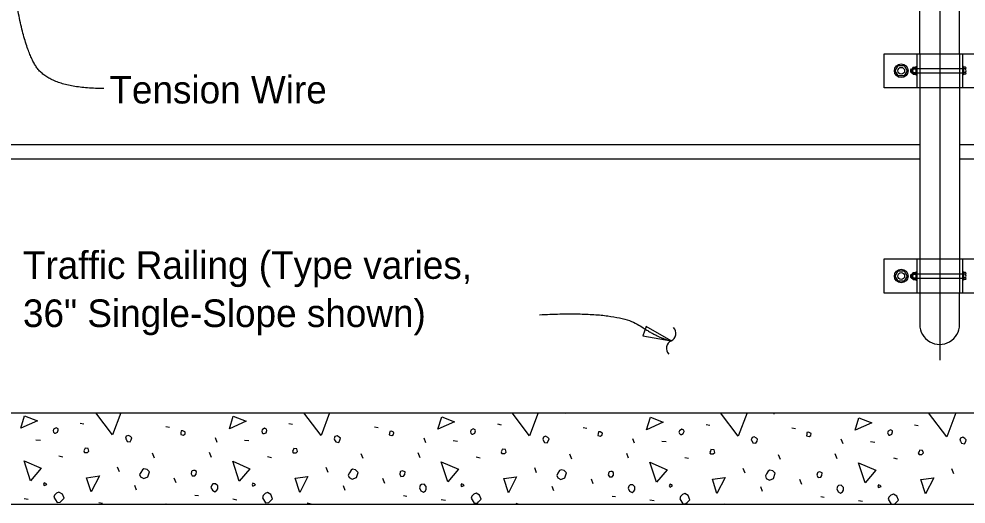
# Model space of a CAD drawing. Extents: x 0 to 41.1, y 0 to 26.4.
# Drawn here: x 5.48 to 12.4, y 13.8 to 17.35 of the extents above; entities that cross this region are included whole.
import ezdxf

# ---------------------------------------------------------------- set-up
doc = ezdxf.new("R2010")
doc.units = 0
for name, color, linetype in [('CL_Major', 7, 'Continuous'), ('Dimension', 7, 'Continuous'), ('Miscellaneous', 7, 'Continuous'), ('SteelMisc', 7, 'Continuous'), ('SteelMisc_h', 7, 'Continuous'), ('SupstrConc', 7, 'Continuous'), ('TextStructures', 7, 'Continuous')]:
    doc.layers.add(name, color=color, linetype=linetype)

msp = doc.modelspace()

# ---------------------------------------------------------------- linework, layer by layer
at = {"layer": 'CL_Major'}
msp.add_line((12.2062, 25.2199), (12.2062, 14.8548), dxfattribs=at)
at = {"layer": 'Dimension'}
msp.add_lwpolyline([(10.2447, 14.9952), (10.0611, 15.0997), (10.0369, 15.0334)], close=True, dxfattribs=at)
for centre, start, end in [((10.2205, 15.0503), 294.14658, 45.87379), ((10.2692, 14.9415), 114.14657, 225.87379)]:
    msp.add_arc(centre, 0.0596, start, end, dxfattribs=at)
for points in [[(6.1, 16.8398), (5.7021, 16.8398), (5.4981, 17.1768), (5.4369, 17.6337)], [(9.284, 15.1869), (9.8469, 15.2152), (10.1683, 15.0071), (10.2449, 14.9959)]]:
    msp.add_open_spline(points, degree=2, dxfattribs=at)
at = {"layer": 'Miscellaneous'}
for p, q in [((11.9986, 16.9625), (11.9986, 16.9746)), ((12.0044, 16.9625), (12.0044, 16.9746)), ((11.9986, 15.4625), (11.9986, 15.4746)), ((12.0044, 15.4625), (12.0044, 15.4746)), ((7.9504, 14.4659), (7.9491, 14.4695)), ((9.4742, 14.4624), (9.4716, 14.4695)), ((10.9981, 14.4588), (10.9942, 14.4695)), ((5.9281, 14.3952), (5.9546, 14.3899)), ((7.4519, 14.3917), (7.4784, 14.3864)), ((6.5539, 14.3705), (6.5804, 14.3652)), ((8.0777, 14.3669), (8.1042, 14.3616)), ((8.9757, 14.3881), (9.0023, 14.3828)), ((9.6015, 14.3634), (9.628, 14.3581)), ((10.4996, 14.3846), (10.5261, 14.3793)), ((11.1253, 14.3599), (11.1519, 14.3545)), ((12.0234, 14.3811), (12.0499, 14.3758)), ((5.6046, 14.2732), (5.6364, 14.2697)), ((6.9287, 14.2538), (6.9163, 14.2874)), ((7.1284, 14.2697), (7.1602, 14.2662)), ((8.4525, 14.2502), (8.4401, 14.2838)), ((8.6522, 14.2662), (8.6841, 14.2626)), ((9.9763, 14.2467), (9.9639, 14.2803)), ((10.1761, 14.2626), (10.2079, 14.2591)), ((11.5001, 14.2432), (11.4877, 14.2768)), ((11.6999, 14.2591), (11.7317, 14.2556)), ((5.7725, 14.1548), (5.8008, 14.1477)), ((6.4708, 14.1389), (6.4567, 14.1742)), ((6.8862, 14.1442), (6.8721, 14.1795)), ((7.2964, 14.1513), (7.3246, 14.1442)), ((7.9946, 14.1353), (7.9805, 14.1707)), ((8.4101, 14.1406), (8.3959, 14.176)), ((8.8202, 14.1477), (8.8485, 14.1406)), ((9.5184, 14.1318), (9.5043, 14.1672)), ((9.9339, 14.1371), (9.9197, 14.1725)), ((10.344, 14.1442), (10.3723, 14.1371)), ((11.0423, 14.1283), (11.0281, 14.1636)), ((11.4577, 14.1336), (11.4435, 14.1689)), ((11.8678, 14.1406), (11.8961, 14.1336)), ((6.2145, 14.0381), (6.2003, 14.0735)), ((7.7383, 14.0346), (7.7242, 14.0699)), ((9.2621, 14.031), (9.248, 14.0664)), ((10.7859, 14.0275), (10.7718, 14.0629)), ((12.3097, 14.024), (12.2956, 14.0593)), ((6.6281, 13.9568), (6.614, 13.9922)), ((8.152, 13.9533), (8.1378, 13.9886)), ((9.6758, 13.9497), (9.6616, 13.9851)), ((11.1996, 13.9462), (11.1854, 13.9815)), ((6.34, 13.9055), (6.3276, 13.9391)), ((7.8638, 13.902), (7.8514, 13.9356)), ((9.3876, 13.8985), (9.3753, 13.9321)), ((10.9114, 13.8949), (10.8991, 13.9285)), ((5.518, 13.8437), (5.548, 13.8384)), ((6.766, 13.8684), (6.7908, 13.8649)), ((7.0418, 13.8401), (7.0719, 13.8348)), ((8.2898, 13.8649), (8.3146, 13.8613)), ((9.8137, 13.8613), (9.8384, 13.8578)), ((11.3375, 13.8578), (11.3622, 13.8543)), ((6.0625, 13.8154), (6.0907, 13.8083)), ((7.5863, 13.8118), (7.6146, 13.8048)), ((8.5656, 13.8366), (8.5957, 13.8313)), ((9.1101, 13.8083), (9.1322, 13.8028)), ((10.0894, 13.8331), (10.1195, 13.8278)), ((10.6339, 13.8048), (10.6418, 13.8028)), ((11.6132, 13.8295), (11.6433, 13.8242))]:
    msp.add_line(p, q, dxfattribs=at)
for points in [[(6.1632, 14.3086), (6.041, 14.4695)], [(6.2233, 14.4695), (6.1632, 14.3086)], [(7.687, 14.305), (7.5621, 14.4695)], [(7.7485, 14.4695), (7.687, 14.305)], [(9.2109, 14.3015), (9.0832, 14.4695)], [(9.2736, 14.4695), (9.2109, 14.3015)], [(10.7347, 14.298), (10.6043, 14.4695)], [(10.7988, 14.4695), (10.7347, 14.298)], [(12.2585, 14.2944), (12.1255, 14.4695)], [(12.3239, 14.4695), (12.2585, 14.2944)], [(5.4932, 14.3563), (5.5215, 14.4482), (5.6152, 14.4111), (5.4932, 14.3563)], [(7.0171, 14.3528), (7.0453, 14.4447), (7.139, 14.4076), (7.0171, 14.3528)], [(8.5409, 14.3492), (8.5692, 14.4412), (8.6628, 14.404), (8.5409, 14.3492)], [(10.0647, 14.3457), (10.093, 14.4376), (10.1867, 14.4005), (10.0647, 14.3457)], [(11.5885, 14.3422), (11.6168, 14.4341), (11.7105, 14.397), (11.5885, 14.3422)], [(5.7407, 14.321), (5.7478, 14.321), (5.7619, 14.328), (5.7672, 14.3439), (5.7655, 14.3528), (5.7513, 14.3599), (5.7337, 14.3492), (5.7301, 14.3386), (5.7337, 14.328), (5.7407, 14.321)], [(6.6617, 14.3121), (6.6812, 14.3068), (6.6935, 14.3157), (6.6953, 14.328), (6.6918, 14.3316), (6.6776, 14.3386), (6.6653, 14.3369), (6.6635, 14.3245), (6.6617, 14.3121)], [(7.2645, 14.3174), (7.2716, 14.3174), (7.2858, 14.3245), (7.2911, 14.3404), (7.2893, 14.3492), (7.2751, 14.3563), (7.2575, 14.3457), (7.2539, 14.3351), (7.2575, 14.3245), (7.2645, 14.3174)], [(8.1855, 14.3086), (8.205, 14.3033), (8.2174, 14.3121), (8.2191, 14.3245), (8.2156, 14.328), (8.2015, 14.3351), (8.1891, 14.3333), (8.1873, 14.321), (8.1855, 14.3086)], [(8.7884, 14.3139), (8.7954, 14.3139), (8.8096, 14.321), (8.8149, 14.3369), (8.8131, 14.3457), (8.799, 14.3528), (8.7813, 14.3422), (8.7777, 14.3316), (8.7813, 14.321), (8.7884, 14.3139)], [(9.7094, 14.305), (9.7288, 14.2997), (9.7412, 14.3086), (9.7429, 14.321), (9.7394, 14.3245), (9.7253, 14.3316), (9.7129, 14.3298), (9.7111, 14.3174), (9.7094, 14.305)], [(10.3122, 14.3104), (10.3192, 14.3104), (10.3334, 14.3174), (10.3387, 14.3333), (10.3369, 14.3422), (10.3228, 14.3492), (10.3051, 14.3386), (10.3016, 14.328), (10.3051, 14.3174), (10.3122, 14.3104)], [(11.2332, 14.3015), (11.2526, 14.2962), (11.265, 14.305), (11.2668, 14.3174), (11.2632, 14.321), (11.2491, 14.328), (11.2367, 14.3263), (11.2349, 14.3139), (11.2332, 14.3015)], [(11.836, 14.3068), (11.8431, 14.3068), (11.8572, 14.3139), (11.8625, 14.3298), (11.8607, 14.3386), (11.8466, 14.3457), (11.8289, 14.3351), (11.8254, 14.3245), (11.8289, 14.3139), (11.836, 14.3068)], [(6.2622, 14.2768), (6.2711, 14.2609), (6.2923, 14.2573), (6.3011, 14.2732), (6.3046, 14.2874), (6.2958, 14.2962), (6.2799, 14.305), (6.264, 14.2997), (6.2587, 14.2838), (6.2622, 14.2768)], [(7.786, 14.2732), (7.7949, 14.2573), (7.8161, 14.2538), (7.8249, 14.2697), (7.8285, 14.2838), (7.8196, 14.2927), (7.8037, 14.3015), (7.7878, 14.2962), (7.7825, 14.2803), (7.786, 14.2732)], [(9.3098, 14.2697), (9.3187, 14.2538), (9.3399, 14.2502), (9.3487, 14.2662), (9.3523, 14.2803), (9.3434, 14.2891), (9.3275, 14.298), (9.3116, 14.2927), (9.3063, 14.2768), (9.3098, 14.2697)], [(10.8337, 14.2662), (10.8425, 14.2502), (10.8637, 14.2467), (10.8726, 14.2626), (10.8761, 14.2768), (10.8672, 14.2856), (10.8513, 14.2944), (10.8354, 14.2891), (10.8301, 14.2732), (10.8337, 14.2662)], [(12.3575, 14.2626), (12.3663, 14.2467), (12.3875, 14.2432), (12.3964, 14.2591), (12.3999, 14.2732), (12.3911, 14.2821), (12.3752, 14.2909), (12.3592, 14.2856), (12.3539, 14.2697), (12.3575, 14.2626)], [(5.9599, 14.1795), (5.9811, 14.1795), (5.9917, 14.1901), (5.9864, 14.2096), (5.9635, 14.2114), (5.9599, 14.2008), (5.9546, 14.1919), (5.9599, 14.1795), (5.9564, 14.1831)], [(7.4837, 14.176), (7.505, 14.176), (7.5156, 14.1866), (7.5103, 14.2061), (7.4873, 14.2078), (7.4837, 14.1972), (7.4784, 14.1884), (7.4837, 14.176), (7.4802, 14.1795)], [(9.0076, 14.1725), (9.0288, 14.1725), (9.0394, 14.1831), (9.0341, 14.2025), (9.0111, 14.2043), (9.0076, 14.1937), (9.0023, 14.1848), (9.0076, 14.1725), (9.004, 14.176)], [(10.5314, 14.1689), (10.5526, 14.1689), (10.5632, 14.1795), (10.5579, 14.199), (10.5349, 14.2008), (10.5314, 14.1901), (10.5261, 14.1813), (10.5314, 14.1689), (10.5278, 14.1725)], [(12.0552, 14.1654), (12.0764, 14.1654), (12.087, 14.176), (12.0817, 14.1954), (12.0587, 14.1972), (12.0552, 14.1866), (12.0499, 14.1778), (12.0552, 14.1654), (12.0517, 14.1689)], [(5.5657, 13.9727), (5.518, 14.1194), (5.6435, 14.0646), (5.5657, 13.9727)], [(7.0895, 13.9692), (7.0418, 14.1159), (7.1673, 14.0611), (7.0895, 13.9692)], [(6.3683, 14.001), (6.3913, 13.9886), (6.4213, 14.001), (6.4337, 14.0381), (6.416, 14.0558), (6.393, 14.0611), (6.3824, 14.054), (6.37, 14.0346), (6.3612, 14.0187), (6.3683, 14.001)], [(6.7377, 14.024), (6.7466, 14.0081), (6.766, 14.0098), (6.7749, 14.0222), (6.7766, 14.0417), (6.7643, 14.047), (6.7554, 14.0487), (6.7448, 14.0452), (6.7413, 14.0417), (6.7377, 14.024)], [(7.8921, 13.9975), (7.9151, 13.9851), (7.9451, 13.9975), (7.9575, 14.0346), (7.9398, 14.0523), (7.9168, 14.0576), (7.9062, 14.0505), (7.8939, 14.031), (7.885, 14.0151), (7.8921, 13.9975)], [(8.6133, 13.9656), (8.5656, 14.1124), (8.6911, 14.0576), (8.6133, 13.9656)], [(9.4159, 13.9939), (9.4389, 13.9815), (9.4689, 13.9939), (9.4813, 14.031), (9.4636, 14.0487), (9.4407, 14.054), (9.4301, 14.047), (9.4177, 14.0275), (9.4088, 14.0116), (9.4159, 13.9939)], [(10.1372, 13.9621), (10.0894, 14.1088), (10.2149, 14.054), (10.1372, 13.9621)], [(10.9397, 13.9904), (10.9627, 13.978), (10.9928, 13.9904), (11.0051, 14.0275), (10.9875, 14.0452), (10.9645, 14.0505), (10.9539, 14.0434), (10.9415, 14.024), (10.9327, 14.0081), (10.9397, 13.9904)], [(11.661, 13.9586), (11.6132, 14.1053), (11.7388, 14.0505), (11.661, 13.9586)], [(6.0077, 13.8914), (5.9741, 13.9957), (6.0678, 14.0081), (6.0077, 13.8914)], [(7.5315, 13.8879), (7.4979, 13.9922), (7.5916, 14.0045), (7.5315, 13.8879)], [(8.2616, 14.0204), (8.2704, 14.0045), (8.2898, 14.0063), (8.2987, 14.0187), (8.3005, 14.0381), (8.2881, 14.0434), (8.2792, 14.0452), (8.2686, 14.0417), (8.2651, 14.0381), (8.2616, 14.0204)], [(9.0553, 13.8843), (9.0217, 13.9886), (9.1154, 14.001), (9.0553, 13.8843)], [(9.7854, 14.0169), (9.7942, 14.001), (9.8137, 14.0028), (9.8225, 14.0151), (9.8243, 14.0346), (9.8119, 14.0399), (9.8031, 14.0417), (9.7924, 14.0381), (9.7889, 14.0346), (9.7854, 14.0169)], [(10.5791, 13.8808), (10.5455, 13.9851), (10.6392, 13.9975), (10.5791, 13.8808)], [(11.3092, 14.0134), (11.318, 13.9975), (11.3375, 13.9992), (11.3463, 14.0116), (11.3481, 14.031), (11.3357, 14.0363), (11.3269, 14.0381), (11.3163, 14.0346), (11.3127, 14.031), (11.3092, 14.0134)], [(12.1029, 13.8772), (12.0693, 13.9815), (12.163, 13.9939), (12.1029, 13.8772)], [(5.6647, 13.9374), (5.6842, 13.9462), (5.6771, 13.9533), (5.6647, 13.9586), (5.6594, 13.9462), (5.6647, 13.9374)], [(6.8827, 13.925), (6.8933, 13.9038), (6.911, 13.8932), (6.9251, 13.9038), (6.9322, 13.9144), (6.9322, 13.9356), (6.9163, 13.9515), (6.8968, 13.9497), (6.888, 13.9409), (6.8827, 13.925)], [(7.1885, 13.9338), (7.208, 13.9427), (7.2009, 13.9497), (7.1885, 13.955), (7.1832, 13.9427), (7.1885, 13.9338)], [(8.4065, 13.9214), (8.4171, 13.9002), (8.4348, 13.8896), (8.4489, 13.9002), (8.456, 13.9108), (8.456, 13.9321), (8.4401, 13.948), (8.4207, 13.9462), (8.4118, 13.9374), (8.4065, 13.9214)], [(8.7123, 13.9303), (8.7318, 13.9391), (8.7247, 13.9462), (8.7123, 13.9515), (8.707, 13.9391), (8.7123, 13.9303)], [(9.9303, 13.9179), (9.9409, 13.8967), (9.9586, 13.8861), (9.9728, 13.8967), (9.9798, 13.9073), (9.9798, 13.9285), (9.9639, 13.9444), (9.9445, 13.9427), (9.9356, 13.9338), (9.9303, 13.9179)], [(10.2362, 13.9267), (10.2556, 13.9356), (10.2485, 13.9427), (10.2362, 13.948), (10.2309, 13.9356), (10.2362, 13.9267)], [(11.4541, 13.9144), (11.4648, 13.8932), (11.4824, 13.8826), (11.4966, 13.8932), (11.5036, 13.9038), (11.5036, 13.925), (11.4877, 13.9409), (11.4683, 13.9391), (11.4594, 13.9303), (11.4541, 13.9144)], [(11.76, 13.9232), (11.7794, 13.9321), (11.7723, 13.9391), (11.76, 13.9444), (11.7547, 13.9321), (11.76, 13.9232)], [(5.7354, 13.8525), (5.7584, 13.8154), (5.7814, 13.8171), (5.7902, 13.826), (5.8097, 13.8454), (5.7973, 13.8755), (5.7725, 13.8896), (5.7549, 13.8826), (5.7407, 13.8684), (5.7354, 13.8525)], [(7.2592, 13.849), (7.2822, 13.8118), (7.3052, 13.8136), (7.314, 13.8224), (7.3335, 13.8419), (7.3211, 13.8719), (7.2964, 13.8861), (7.2787, 13.879), (7.2645, 13.8649), (7.2592, 13.849)], [(8.7831, 13.8454), (8.806, 13.8083), (8.829, 13.8101), (8.8379, 13.8189), (8.8573, 13.8384), (8.8449, 13.8684), (8.8202, 13.8826), (8.8025, 13.8755), (8.7884, 13.8613), (8.7831, 13.8454)], [(10.3069, 13.8419), (10.3298, 13.8048), (10.3528, 13.8065), (10.3617, 13.8154), (10.3811, 13.8348), (10.3687, 13.8649), (10.344, 13.879), (10.3263, 13.8719), (10.3122, 13.8578), (10.3069, 13.8419)], [(11.8738, 13.8028), (11.8766, 13.803), (11.8855, 13.8118), (11.9049, 13.8313), (11.8926, 13.8613), (11.8678, 13.8755), (11.8501, 13.8684), (11.836, 13.8543), (11.8307, 13.8384)], [(11.8307, 13.8384), (11.8527, 13.8028)], [(6.5568, 13.8028), (6.5557, 13.803), (6.5541, 13.8028)]]:
    msp.add_lwpolyline(points, dxfattribs=at)
at = {"layer": 'SteelMisc'}
for p, q in [((12.0604, 17.0944), (12.0604, 17.6079)), ((12.3521, 17.0944), (12.3521, 17.6079)), ((11.8002, 17.0944), (12.6122, 17.0944)), ((11.8002, 16.8444), (11.8002, 17.0944)), ((12.0396, 17.0944), (12.0396, 16.8444)), ((12.3729, 17.0944), (12.3729, 16.8444)), ((11.9958, 16.9774), (12.0015, 16.984)), ((11.9958, 16.9597), (11.9958, 16.9774)), ((11.9958, 16.9597), (12.0015, 16.9541)), ((12.0015, 16.984), (12.008, 16.984)), ((12.0015, 16.9541), (12.0015, 16.984)), ((12.0015, 16.9541), (12.008, 16.9541)), ((12.008, 16.9873), (12.008, 16.9516)), ((12.0127, 16.9824), (12.033, 16.9824)), ((12.0127, 16.9565), (12.033, 16.9565)), ((12.0129, 16.9954), (12.033, 16.9954)), ((12.033, 16.9997), (12.033, 16.9391)), ((12.033, 16.9997), (12.0396, 16.9997)), ((12.033, 16.9954), (12.033, 16.9435)), ((12.3792, 16.9997), (12.3731, 16.9997)), ((12.3939, 16.9954), (12.3791, 16.9954)), ((12.394, 16.9824), (12.3791, 16.9824)), ((12.394, 16.9564), (12.3791, 16.9564)), ((12.3792, 16.9997), (12.3792, 16.9391)), ((12.013, 16.9435), (12.033, 16.9435)), ((12.033, 16.9391), (12.0396, 16.9391)), ((12.3792, 16.9391), (12.3731, 16.9391)), ((12.3939, 16.9434), (12.3791, 16.9434)), ((12.6122, 16.8444), (11.8002, 16.8444)), ((12.0604, 16.8444), (12.0604, 15.5944)), ((12.3521, 16.8444), (12.3521, 15.5944)), ((11.8002, 15.5944), (12.6122, 15.5944)), ((11.8002, 15.3444), (11.8002, 15.5944)), ((12.0396, 15.5944), (12.0396, 15.3444)), ((12.3729, 15.5944), (12.3729, 15.3444)), ((12.033, 15.4997), (12.033, 15.4391)), ((12.033, 15.4997), (12.0396, 15.4997)), ((12.3792, 15.4997), (12.3731, 15.4997)), ((12.3792, 15.4997), (12.3792, 15.4391)), ((11.9958, 15.4774), (12.0015, 15.484)), ((11.9958, 15.4597), (11.9958, 15.4774)), ((11.9958, 15.4597), (12.0015, 15.4541)), ((12.0015, 15.484), (12.008, 15.484)), ((12.0015, 15.4541), (12.0015, 15.484)), ((12.0015, 15.4541), (12.008, 15.4541)), ((12.008, 15.4873), (12.008, 15.4516)), ((12.0127, 15.4824), (12.033, 15.4824)), ((12.0127, 15.4565), (12.033, 15.4565)), ((12.0129, 15.4954), (12.033, 15.4954)), ((12.013, 15.4435), (12.033, 15.4435)), ((12.033, 15.4954), (12.033, 15.4435)), ((12.033, 15.4391), (12.0396, 15.4391)), ((12.3792, 15.4391), (12.3731, 15.4391)), ((12.3939, 15.4954), (12.3791, 15.4954)), ((12.394, 15.4824), (12.3791, 15.4824)), ((12.394, 15.4564), (12.3791, 15.4564)), ((12.3939, 15.4434), (12.3791, 15.4434)), ((12.6122, 15.3444), (11.8002, 15.3444)), ((12.0603, 15.3444), (12.0603, 15.1153)), ((12.3519, 15.1153), (12.3519, 15.3444))]:
    msp.add_line(p, q, dxfattribs=at)
for points in [[(11.9036, 17.007), (11.9469, 17.007), (11.9686, 16.9694), (11.9469, 16.9319), (11.9036, 16.9319), (11.8819, 16.9694)], [(11.9036, 15.507), (11.9469, 15.507), (11.9686, 15.4694), (11.9469, 15.4319), (11.9036, 15.4319), (11.8819, 15.4694)]]:
    msp.add_lwpolyline(points, close=True, dxfattribs=at)
for centre, radius in [((11.9252, 16.9694), 0.05), ((11.9252, 16.9694), 0.025), ((11.9252, 15.4694), 0.05), ((11.9252, 15.4694), 0.025)]:
    msp.add_circle(centre, radius, dxfattribs=at)
for centre, radius, start, end in [((12.0145, 16.9889), 0.00674, 104.48908, 254.18889), ((12.0274, 16.9694), 0.0196, 138.62797, 221.37203), ((12.0145, 16.95), 0.00673, 105.7823, 255.54039), ((12.3922, 16.9889), 0.00673, 285.7823, 75.54039), ((12.3922, 16.95), 0.00674, 284.48908, 74.18889), ((12.3793, 16.9694), 0.0196, 318.62797, 41.37203), ((12.0145, 15.4889), 0.00674, 104.48908, 254.18889), ((12.0274, 15.4694), 0.0196, 138.62797, 221.37203), ((12.0145, 15.45), 0.00673, 105.7823, 255.54039), ((12.3922, 15.4889), 0.00673, 285.7823, 75.54039), ((12.3922, 15.45), 0.00674, 284.48908, 74.18889), ((12.3793, 15.4694), 0.0196, 318.62797, 41.37203)]:
    msp.add_arc(centre, radius, start, end, dxfattribs=at)
msp.add_ellipse((12.2062, 15.1153), major_axis=(0, 0.1458), ratio=0.999499, start_param=1.570796, end_param=4.712389, dxfattribs=at)
at = {"layer": 'SteelMisc_h'}
for p, q in [((12.0604, 17.0944), (12.0604, 16.8444)), ((12.3521, 17.0944), (12.3521, 16.8444)), ((12.3729, 16.984), (12.008, 16.984)), ((12.008, 16.9541), (12.3729, 16.9541)), ((12.0604, 15.5944), (12.0604, 15.3444)), ((12.3521, 15.5944), (12.3521, 15.3444)), ((12.3729, 15.484), (12.008, 15.484)), ((12.008, 15.4541), (12.3729, 15.4541))]:
    msp.add_line(p, q, dxfattribs=at)
at = {"layer": 'SupstrConc'}
for p, q in [((2.352, 16.4295), (12.0604, 16.4295)), ((12.3521, 16.4295), (22.0604, 16.4295)), ((2.352, 16.3254), (12.0604, 16.3254)), ((12.3521, 16.3254), (22.0604, 16.3254)), ((0.8193, 14.4695), (23.5931, 14.4695)), ((0.8193, 13.8028), (23.5931, 13.8028))]:
    msp.add_line(p, q, dxfattribs=at)

# ---------------------------------------------------------------- texts
at = {"layer": 'Dimension'}
for s, p in [('Traffic Railing (Type varies,', (5.5094, 15.4486)), ('36" Single-Slope shown)', (5.5094, 15.0966))]:
    msp.add_text(s, height=0.2016, dxfattribs=at).set_placement(p)
at = {"layer": 'TextStructures'}
msp.add_text('Tension Wire', height=0.2016, dxfattribs=at).set_placement((6.1409, 16.7305))

doc.saveas('drawing.dxf')
